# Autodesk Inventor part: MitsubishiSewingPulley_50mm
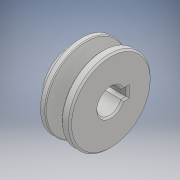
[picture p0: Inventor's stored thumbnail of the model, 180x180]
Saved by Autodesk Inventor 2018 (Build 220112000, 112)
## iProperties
Created: 2018-08
Part Number: MitsubishiSewingPulley_50mm
Material: Generic
Document SubType Name: Modeling
Designer: Bill
Density: 1 g/cm^3
Appearance: Default
Author: Bill
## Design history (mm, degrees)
sketch "Sketch1"
  geometry: L1 (-34.237, 0)-(37.609, 0) reference; L2 (-10, -7.585)-(-10, -25); L3 (15.5, -16.25)-(15.5, -7.585); L4 (-10, -25)-(-5, -25); L5 (-5, -25)-(-1.5, -14.1); L6 (1.5, -14.1)-(5, -25); L7 (5, -25)-(8, -25); L8 (0, 0)-(0, -91.677); L9 (1.5, -14.1)-(-1.5, -14.1); L10 (15.5, -7.585)-(-10, -7.585); L11 (15.5, -16.25)-(8, -25)
  constraints: 22 end point, 3 horizontal, 3 perpendicular, 2 point on line, 2 vertical
  dimensions: "d0" = 25.5 distance between parallel lines of L3 L2; "d1" = 5 distance from line of L4.end L2; "d2" = 18 distance of L7.end L2.end; "d3" = 10 distance of L6.end L4.end; "d4" = 1.5 distance from line of L8 L6.start; "d5" = 1.5 distance from line of L5.end L8; "d6" = 5 distance from line of L8 L6.end (= 0.5 x d3); "d7" = 10.9 distance between parallel lines of L9 L7; "d8" = 50 diameter of L4 L1; "d10" = 15.17 diameter of L10 L1; "d16" = 32.5 diameter of L3.start L1
revolve "Revolution1" sketch "Sketch1" stored, may be unused: angle "d11" = 90 deg
sketch "Sketch2"
  geometry: L1 (-2.616, 7.12)-(-2.616, 10.246); L2 (-2.616, 10.246)-(2.616, 10.246); L3 (2.616, 10.246)-(2.616, 7.12); L4 (2.616, 4.924)-(-2.616, 10.246); L5 (-2.616, 4.924)-(2.616, 10.246); A1 r 7.585 centre (0, 0) between (2.616, 7.12) and (-2.616, 7.12); 3 further points
  constraints: 10 end point, 2 midpoint, 2 point on circle, 1 centre point, 1 coincident, 1 parallel, 1 vertical alignment, 1 other
  dimensions: "d12" = 5.2324 distance of L1.end L2.end; "d13" = 17.8308 dimension on L2
extrude "Extrusion1" cut sketch "Sketch2" extent not by distance; stored distance "d14" = 10; taper "d15" = 0 deg
chamfer "Chamfer1" distance "d17" = 1; stored, may be unused: second distance "d18" = 2, angle "d19" = 45 deg
chamfer "Chamfer2" distance "d20" = 1; stored, may be unused: second distance "d21" = 2, angle "d22" = 45 deg
fillet "Fillet1" dims "d23" = 0.6
fillet "Fillet2" dims "d24" = 0.6
body "Solid1"
